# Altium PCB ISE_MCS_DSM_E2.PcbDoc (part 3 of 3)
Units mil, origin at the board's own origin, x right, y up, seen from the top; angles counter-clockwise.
Board outline 7874.02 x 2559.06 mil, 4 copper layers (Top Layer, MidLayer1, MidLayer2, Bottom Layer), stack 61.2 mil thick; 400 components, 190 nets, 1028 pads, 191 vias.
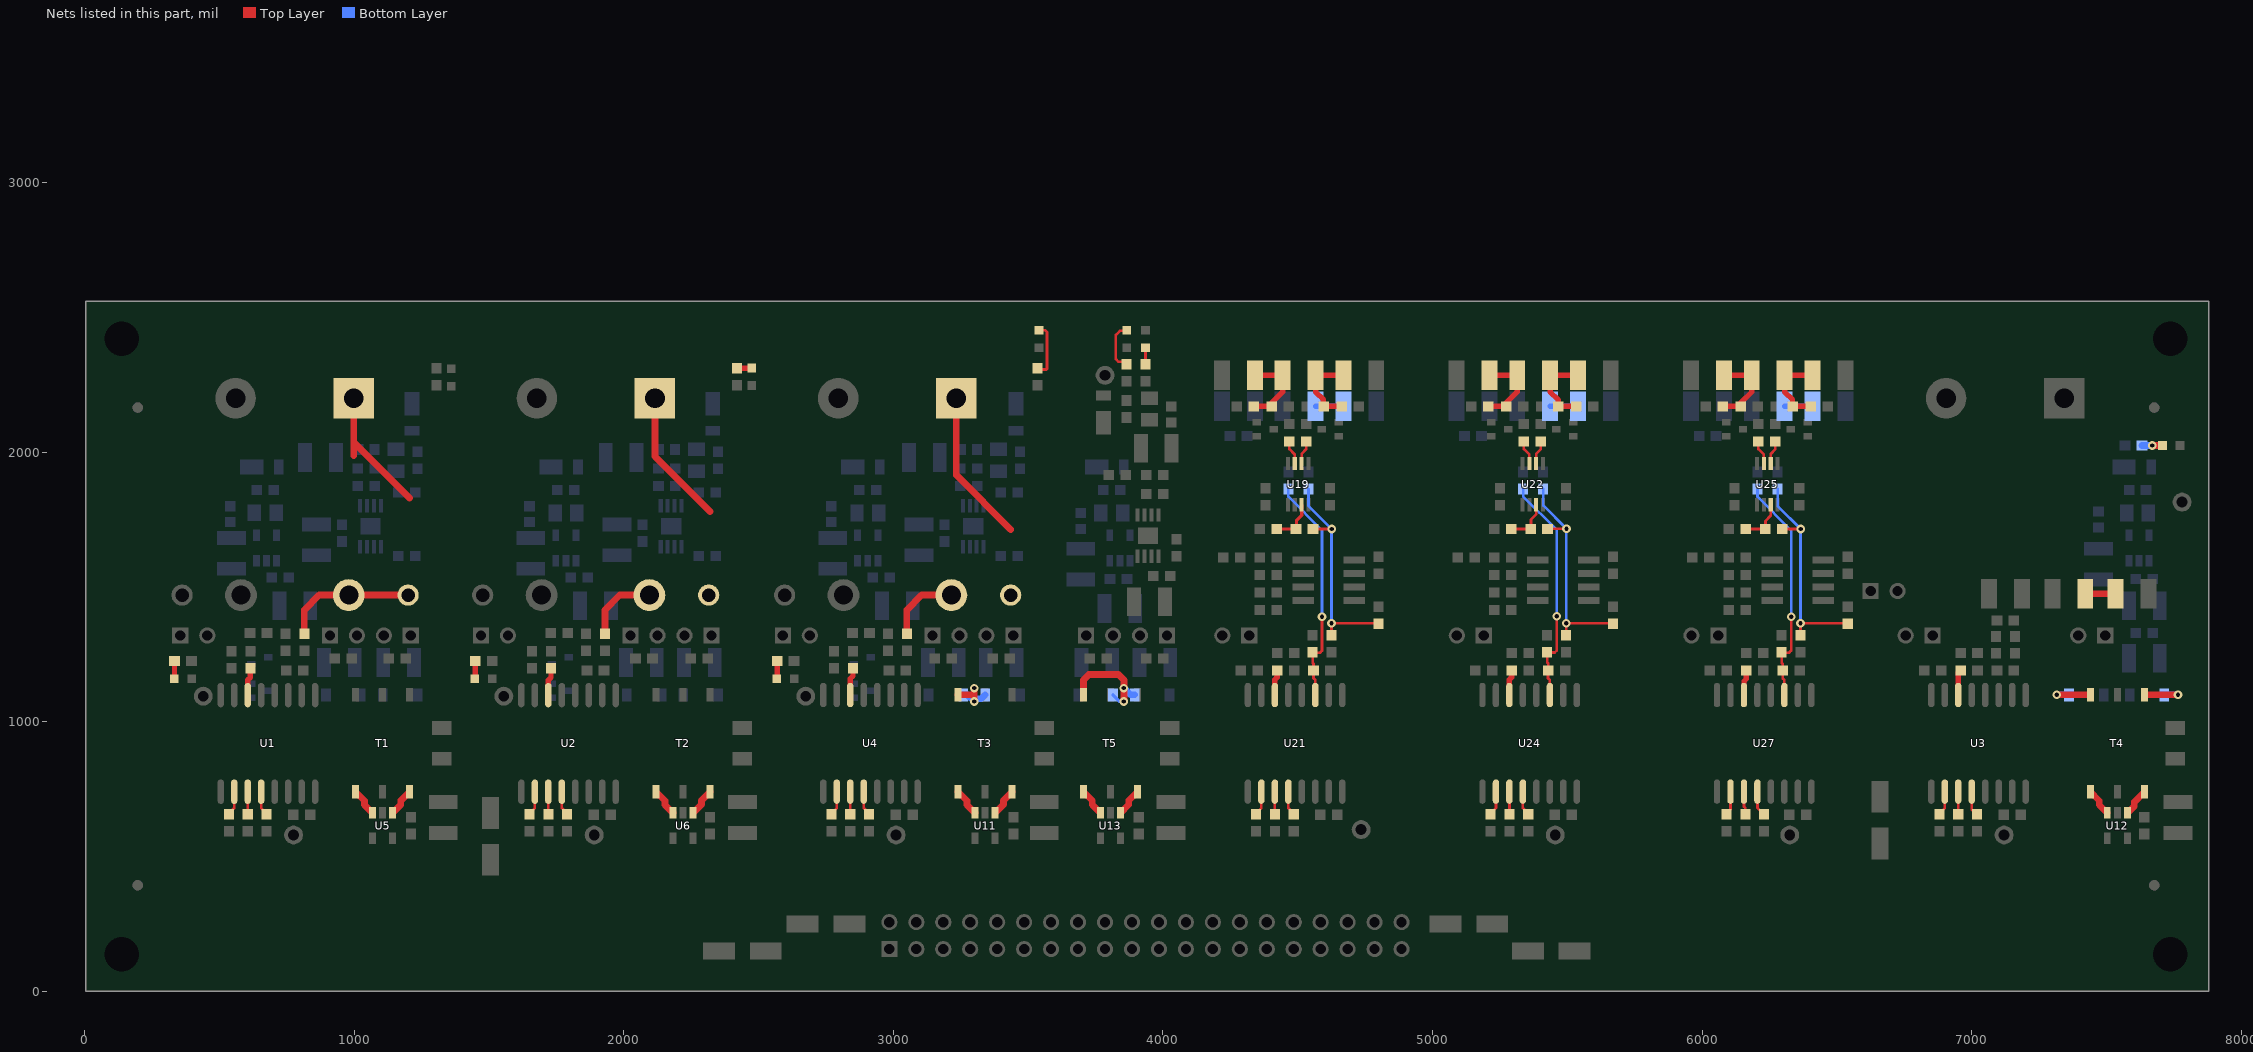
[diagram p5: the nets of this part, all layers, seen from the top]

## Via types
v1: diameter 32, hole 16, Top Layer to Bottom Layer, tented both sides, 191 vias

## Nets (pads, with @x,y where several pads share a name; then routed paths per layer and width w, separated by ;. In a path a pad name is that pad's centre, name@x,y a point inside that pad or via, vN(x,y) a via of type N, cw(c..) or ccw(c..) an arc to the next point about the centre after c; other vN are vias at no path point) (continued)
NetD14_1: D14.1 R35.1 | length 55.8
  Top Layer w20: R35.1@2420,2311.5 2472.98,2311.5 D14.1@2475,2309.48
NetD17_2: D17.2 R40.1 | length 65.4
  Top Layer w20: D17.2@332.52,1160 333.5,1160.98 R40.1@333.5,1225
NetD18_2: D18.2 R41.1 | length 65.4
  Top Layer w20: D18.2@1447.52,1160 1448.5,1160.98 R41.1@1448.5,1225
NetD19_2: D19.2 D23.1 T3.6 | length 212.7
  Top Layer w25: T3.6@3240,1099.84 3294.84,1099.84 3295,1100 ; v1(3300,1075) v1(3300,1125)
  Bottom Layer w25: D19.2@3259.47,1100 3275,1100 v1(3300,1075) 3300,1085 3325.53,1085 D23.1@3340.53,1100
NetD20_2: D20.2 T4.6 | length 170.6
  Top Layer w25: v1(7315.16,1099.84) T4.6@7440,1099.84
  Bottom Layer w25: v1(7315.16,1099.84) 7315,1100 D20.2@7360.53,1100
NetD21_2: D21.2 D24.1 T5.6 | length 403.5
  Top Layer w25: T5.6@3705,1099.84 3705,1155 3725,1175 3835,1175 3855,1155 v1(3855,1125) v1(3855,1075)
  Bottom Layer w12: D21.2@3814.47,1100 3839.47,1075 v1(3855,1075)
  Bottom Layer w25: v1(3855,1125) 3880,1100 D24.1@3895.53,1100
NetD22_2: D22.2 T4.4 | length 175.3
  Top Layer w25: T4.4@7640,1099.84 v1(7764.84,1099.84)
  Bottom Layer w25: D22.2@7714.47,1100 7764.68,1100 v1(7764.84,1099.84)
NetD27_1: D27.1 R42.1 | length 204.5
  Top Layer w10: R42.1@3535,2306.5 3566.5,2306.5 3570,2310 3570,2445 3562.52,2452.48 D27.1@3540,2452.48
NetD28_1: D28.1 R43.1 | length 180.4
  Top Layer w10: R43.1@3865,2335 3835,2335 3825,2345 3825,2435 3840,2450 D28.1@3865,2450
NetD32_2: D32.2 R48.1 | length 65.4
  Top Layer w20: D32.2@2567.52,1160.31 2568.5,1161.3 R48.1@2568.5,1225.31
NetD33_2: D33.2 R49.1 | length 76
  Top Layer w25: v1(7670,2025) D33.2@7707.52,2025
  Bottom Layer w25: R49.1@7631.5,2025 v1(7670,2025)
NetD34_2: D34.2 R50.1 | length 68.5
  Top Layer w10: R50.1@3935,2326.5 D34.2@3935,2387.52 D34.2@3935,2395
NetR5_1: R5.1 U1.12 | length 88.8
  Top Layer w10: U1.12@655,740.55 655,680 R5.1@675,660
NetR6_2: R6.2 U1.6 | length 103.8
  Top Layer w20: U1.6@605,1098.82 605,1155 615,1165 R6.2@615,1198.5
NetR7_1: R7.1 U1.11 | length 87.6
  Top Layer w10: U1.11@605,740.55 605,660 R7.1@610,655
NetR8_1: R8.1 U1.10 | length 95.9
  Top Layer w10: R8.1@530,655 555,680 U1.10@555,740.55
NetR13_1: R13.1 U2.12 | length 93.8
  Top Layer w10: U2.12@1770,740.55 1770,680 1790,660 R13.1@1790,656.5 R13.1@1790,655
NetR14_2: R14.2 U2.6 | length 103.8
  Top Layer w20: U2.6@1720,1098.82 1720,1155 1730,1165 R14.2@1730,1198.5
NetR15_1: R15.1 U2.11 | length 95.6
  Top Layer w10: R15.1@1720,645 U2.11@1720,740.55
NetR16_1: R16.1 U2.10 | length 98.8
  Top Layer w10: R16.1@1650,650 1650,660 1670,680 U2.10@1670,740.55
NetR17_2: R17.2 R18.1 | length 113
  Top Layer w25: R18.1@7421.02,1475 R17.2@7533.98,1475
NetR25_1: R25.1 U3.12 | length 94.2
  Top Layer w10: U3.12@7000,740.87 7000,675 R25.1@7020,655
NetR26_2: R26.2 U3.6 | length 94.4
  Top Layer w20: U3.6@6950,1099.13 6950,1181.5 R26.2@6958.5,1190
NetR27_1: R27.1 U3.11 | length 85.9
  Top Layer w10: R27.1@6950,655 R27.1@6950,656.5 U3.11@6950,740.87
NetR28_1: R28.1 U3.10 | length 94.2
  Top Layer w10: R28.1@6880,655 R28.1@6880,656.5 6880,660 6900,680 U3.10@6900,740.87
NetR30_1: R30.1 U4.12 | length 94.2
  Top Layer w10: U4.12@2890,740.87 2890,680 2910,660 R30.1@2910,656.5 R30.1@2910,655
NetR31_2: R31.2 U4.6 | length 103.5
  Top Layer w20: U4.6@2840,1099.13 2840,1160 2850,1170 R31.2@2850,1198.5
NetR32_1: R32.1 U4.11 | length 85.9
  Top Layer w10: R32.1@2840,655 R32.1@2840,656.5 U4.11@2840,740.87
NetR33_1: R33.1 U4.10 | length 89.2
  Top Layer w10: R33.1@2770,660 2790,680 U4.10@2790,740.87
NetR51_2: R51.2 R55.1 | length 103
  Bottom Layer w20: R55.1@4566.02,2170 R51.2@4668.98,2170
NetR52_2: R52.2 R53.1 R56.1 R61.1 | length 298.5
  Top Layer w20: R53.1@4663.5,2170 R56.1@4596.5,2170 4595,2170 4595,2195 4566.02,2223.98 R61.1@4566.02,2285 R52.2@4668.98,2285
NetR54_1: R54.1 R63.1 U19.7 | length 172.4
  Top Layer w12: R63.1@4420,1715 R63.1@4421.5,1715 R54.1@4493.5,1715 4495,1715 4495,1746.2 4514.4,1765.6 U19.7@4514.4,1804.4
NetR58_1: R58.1 U19.3 | length 90.6
  Top Layer w10: R58.1@4468.5,2040 4468.5,2011 4468.8,2011 4488.8,1991 U19.3@4488.8,1958
NetR58_2: R58.2 U19.2 | length 89.1
  Top Layer w10: U19.2@4514.4,1958 4514.4,1993.9 4531.5,2011 R58.2@4531.5,2040
NetR61_2: R61.2 R66.1 R70.1 R71.2 | length 307.3
  Top Layer w20: R71.2@4336.5,2170 R66.1@4390,2170 ; R70.1@4341.02,2285 R61.2@4443.98,2285 4443.98,2223.98 R66.1@4390,2170 ; R66.1@4403.5,2170 R66.1@4390,2170
NetR69_1: R69.1 U21.12 | length 94.2
  Top Layer w10: U21.12@4465,740.87 4465,680 4485,660 R69.1@4485,656.5 R69.1@4485,655
NetR72_2: R72.2 U21.6 | length 94.4
  Top Layer w20: U21.6@4415,1099.13 4415,1156.73 4423.5,1165.24 R72.2@4423.5,1190
NetR73_1: R73.1 U21.11 | length 85.9
  Top Layer w10: R73.1@4415,655 R73.1@4415,656.5 U21.11@4415,740.87
NetR74_1: R74.1 U21.10 | length 94.2
  Top Layer w10: R74.1@4345,655 R74.1@4345,656.5 4345,660 4365,680 U21.10@4365,740.87
NetR75_2: R75.2 R79.1 | length 103
  Bottom Layer w20: R79.1@5436.02,2170 R75.2@5538.98,2170
NetR76_2: R76.2 R77.1 R80.1 R87.1 | length 297.6
  Top Layer w20: R77.1@5533.5,2170 R80.1@5466.5,2170 5466.5,2193.5 5436.02,2223.98 R87.1@5436.02,2285 R76.2@5538.98,2285
NetR78_1: R78.1 R85.1 U22.7 | length 173
  Top Layer w10: R85.1@5290,1715 R85.1@5291.5,1715 R78.1@5363.5,1715 5365,1715 5365,1750 5384.4,1769.4 U22.7@5384.4,1804.4 ; U22.7@5385,1804.4 U22.7@5385,1805
NetR82_1: R82.1 U22.3 | length 90.6
  Top Layer w10: R82.1@5338.5,2040 5338.5,2011 5338.8,2011 5358.8,1991 U22.3@5358.8,1958
NetR82_2: R82.2 U22.2 | length 89.1
  Top Layer w10: U22.2@5384.4,1958 5384.4,1993.9 5401.5,2011 R82.2@5401.5,2040
NetR87_2: R87.2 R90.1 R94.1 R95.2 | length 303.2
  Top Layer w20: R95.2@5205,2170 R95.2@5206.5,2170 R90.1@5273.5,2170 5273.5,2183.5 5313.98,2223.98 R87.2@5313.98,2285 R94.1@5211.02,2285
NetR93_1: R93.1 U24.12 | length 94.2
  Top Layer w10: U24.12@5335,740.87 5335,680 5355,660 R93.1@5355,656.5 R93.1@5355,655
NetR96_2: R96.2 U24.6 | length 94.4
  Top Layer w20: U24.6@5285,1099.13 5285,1156.73 5293.5,1165.24 R96.2@5293.5,1190
NetR97_1: R97.1 U24.11 | length 85.9
  Top Layer w10: R97.1@5285,655 R97.1@5285,656.5 U24.11@5285,740.87
NetR98_1: R98.1 U24.10 | length 94.2
  Top Layer w10: R98.1@5215,655 R98.1@5215,656.5 5215,660 5235,680 U24.10@5235,740.87
NetR99_2: R99.2 R103.1 | length 103
  Bottom Layer w20: R103.1@6306.02,2170 R99.2@6408.98,2170
NetR100_2: R100.2 R101.1 R104.1 R111.1 | length 297
  Top Layer w20: R104.1@6335,2170 6335,2195 6306.02,2223.98 R111.1@6306.02,2285 R100.2@6408.98,2285 ; R104.1@6336.5,2170 R101.1@6403.5,2170
NetR102_1: R102.1 R109.1 U25.7 | length 170.9
  Top Layer w10: R109.1@6161.5,1715 R102.1@6233.5,1715 6235,1715 6235,1745 6254.4,1764.4 U25.7@6254.4,1804.4
NetR106_1: R106.1 U25.3 | length 90.6
  Top Layer w10: R106.1@6208.5,2040 6208.5,2011 6208.8,2011 6228.8,1991 U25.3@6228.8,1958
NetR106_2: R106.2 U25.2 | length 89.1
  Top Layer w10: U25.2@6254.4,1958 6254.4,1993.9 6271.5,2011 R106.2@6271.5,2040
NetR111_2: R111.2 R114.1 R118.1 R119.2 | length 301.7
  Top Layer w20: R119.2@6076.5,2170 R114.1@6143.5,2170 6143.5,2183.5 6183.98,2223.98 R111.2@6183.98,2285 R118.1@6081.02,2285
NetR117_1: R117.1 U27.12 | length 96.2
  Top Layer w10: U27.12@6205,740.87 6205,680 R117.1@6230,655
NetR120_2: R120.2 U27.6 | length 94.4
  Top Layer w20: U27.6@6155,1099.13 6155,1150 6163.5,1158.5 R120.2@6163.5,1190
NetR121_1: R121.1 U27.11 | length 82.9
  Top Layer w10: U27.11@6155,740.87 6155,685 6160,680 R121.1@6160,660
NetR122_1: R122.1 U27.10 | length 92.1
  Top Layer w10: R122.1@6090,655 R122.1@6090,656.5 6090,660 6105,675 U27.10@6105,740.87
NetT1_1: T1.1 U5.3 | length 103.7
  Top Layer w25: T1.1@1005,740 1038,707 1038,691.84 U5.3@1067.6,662.24
NetT1_3: T1.3 U5.1 | length 103.7
  Top Layer w25: U5.1@1142.4,662.24 1173,692.84 1173,708 T1.3@1205,740
NetT2_1: T2.1 U6.3 | length 103.7
  Top Layer w25: T2.1@2120,740 2153,707 2153,691.84 U6.3@2182.6,662.24
NetT2_3: T2.3 U6.1 | length 103.7
  Top Layer w25: U6.1@2257.4,662.24 2288,692.84 2288,708 T2.3@2320,740
NetT3_1: T3.1 U11.3 | length 103.7
  Top Layer w25: T3.1@3240,740 3273,707 3273,691.84 U11.3@3302.6,662.24
NetT3_3: T3.3 U11.1 | length 103.7
  Top Layer w25: U11.1@3377.4,662.24 3408,692.84 3408,708 T3.3@3440,740
NetT4_1: T4.1 U12.3 | length 103.7
  Top Layer w25: T4.1@7440,740 7473,707 7473,691.84 U12.3@7502.6,662.24
NetT4_3: T4.3 U12.1 | length 103.7
  Top Layer w25: U12.1@7577.4,662.24 7603,687.84 7603,703 T4.3@7640,740
NetT5_1: T5.1 U13.3 | length 103.7
  Top Layer w25: T5.1@3705,740 3738,707 3738,691.84 U13.3@3767.6,662.24
NetT5_3: T5.3 U13.1 | length 103.7
  Top Layer w25: U13.1@3842.4,662.24 3873,692.84 3873,708 T5.3@3905,740
U_OUT: J2.1 R1.1 R2.1 R3.1 | length 967
  Top Layer w25: R1.1@815,1326.5 815,1415 870,1470 R2.1@980,1470 R3.1@1200,1470 R3.1@1205,1470 ; 998,1987 J2.1@998,2160 ; 998,2037 1205,1830
V_OUT: J4.1 R9.1 R10.1 R11.1 | length 741
  Top Layer w25: R9.1@1930,1326.5 1930,1415 1985,1470 R10.1@2095,1470 ; J4.1@2115.4,2160 2115.4,1984.6 2320,1780
VOLT_U_PH: R54.2 R57.2 R59.2 R60.1 | length 823.6
  Top Layer w10: R54.2@4556.5,1715 v1(4625.75,1715) ; R60.1@4625,1321.5 v1(4625,1365) 4800,1365 R59.2@4800,1363.5
  Bottom Layer w10: R57.2@4540,1863.5 4540,1800.75 v1(4625.75,1715) 4625,1714.25 v1(4625,1365)
VOLT_U_PH_N: C115.2 R65.2 R67.1 U21.3 | length 848.4
  Top Layer w10: U21.3@4565,1105 4565,1155 4558.5,1161.5 C115.2@4558.5,1190 4558.5,1214.7 4555,1218.2 R67.1@4555,1258.5 4557.5,1256 4582.2,1256 4590,1263.8 v1(4590,1390)
  Bottom Layer w10: R65.2@4465,1863.5 4465,1835 4590,1710 v1(4590,1390)
VOLT_V_PH: R78.2 R81.2 R83.2 R84.1 | length 823.6
  Top Layer w10: R78.2@5427.39,1715.9 v1(5496.64,1715.9) ; R84.1@5495.9,1322.39 v1(5495.9,1365.9) 5670.9,1365.9 R83.2@5670.9,1364.4
  Bottom Layer w10: R81.2@5410.9,1864.4 5410.9,1801.64 v1(5496.64,1715.9) 5495.9,1715.15 v1(5495.9,1365.9)
VOLT_V_PH_N: C127.2 R89.2 R91.1 U24.3 | length 848.4
  Top Layer w10: C127.2@5428.5,1190 5428.5,1161.5 5435,1155 U24.3@5435,1105 ; C127.2@5429.4,1190.9 5429.4,1215.59 5425.9,1219.1 5425.9,1259.4 5428.4,1256.9 5453.1,1256.9 5460.9,1264.7 v1(5460.9,1390.9)
  Bottom Layer w10: R89.2@5335.9,1864.4 5335.9,1835.9 5460.9,1710.9 v1(5460.9,1390.9)
VOLT_W_PH: R102.2 R105.2 R107.2 R108.1 | length 823.6
  Top Layer w10: R102.2@6296.5,1715 v1(6365.75,1715) ; R108.1@6365,1321.5 v1(6365,1365) 6540,1365 R107.2@6540,1363.5
  Bottom Layer w10: R105.2@6280,1863.5 6280,1800.75 v1(6365.75,1715) 6365,1714.25 v1(6365,1365)
VOLT_W_PH_N: C139.2 R113.2 R115.1 U27.3 | length 843.4
  Top Layer w10: U27.3@6305,1110 6305,1155 6298.5,1161.5 C139.2@6298.5,1190 6298.5,1214.7 6295,1218.2 R115.1@6295,1258.5 6297.5,1256 6322.2,1256 6330,1263.8 v1(6330,1390)
  Bottom Layer w10: R113.2@6205,1863.5 6205,1835 6330,1710 v1(6330,1390)
W_OUT: J8.1 R20.1 R23.1 R24.1 | length 806.2
  Top Layer w25: R20.1@3050,1326.5 3050,1415 3105,1470 R23.1@3215,1470 ; J8.1@3233.51,2160 3233.51,1915 3435,1713.51
pads on no net: FID1.1 FID2.1 FID3.1 FID4.1 FID5.1 FID6.1 FID7.1 FID8.1 LBL1.0 Logo1.0 MH1.1 MH2.1 MH3.1 MH4.1 T1.5 T2.5 T3.5 T5.5 U1.1 U1.4 U1.5 U1.15 U2.1 U2.4 U2.5 U2.15 U3.1 U3.4 U3.5 U3.15 U4.1 U4.4 U4.5 U4.15 U7.7 U8.7 U9.4 U9.5 U10.4 U10.5 U14.7 U15.7 U16.4 U16.5 U17.4 U17.5 U18.4 U18.5 U20.1 U20.5 U20.8 U21.1 U21.4 U21.5 U21.15 U23.1 U23.5 U23.8 U24.1 U24.4 U24.5 U24.15 U26.1 U26.5 U26.8 U27.1 U27.4 U27.5 U27.15

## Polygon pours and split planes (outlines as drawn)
+5.0V_VDC on MidLayer1 "MidLayer1-No Net 8" (solid, remove dead copper, pour order 73): 6695,2075 7835,2075 7835,1055 6695,1055
-5.0V_PH on MidLayer1 "MidLayer1-No Net 1" (solid, remove dead copper, pour order 52): 3750,2335 4010,2335 4010,2169.97 4075,2104.97 4075.03,2105 6580,2105 6580,1055 4175,1055 4155,1075 4155,1630 4025,1760 3750,1760
+3.3V_DVDD on MidLayer1 "MidLayer1-No Net" (solid, remove dead copper, pour order 45): 45,785 7830,785 7830,45 45,45
U_OUT on MidLayer1 "MidLayer1-No Net 2" (solid, remove dead copper, pour order 56): 860,2275 785,2200 785,1470 850,1405 1195,1405 1260,1470 1259.06,2090.94 1075,2275
GND_USH on MidLayer1 "MidLayer1-No Net 5" (solid, remove dead copper, pour order 65): 615,1405 680,1470 680,2205 610,2275 515,2275 305,2065 305,1470 370,1405
GND_VSH on MidLayer1 "MidLayer1-No Net 6" (solid, remove dead copper, pour order 66): 1735,1405 1800,1470 1800,2200 1725,2275 1640,2275 1420,2055 1420,1470 1485,1405
V_OUT on MidLayer1 "MidLayer1-No Net 3" (solid, remove dead copper, pour order 57): 1965,1405 1900,1470 1900,2200 1975,2275 2190.04,2275 2375.04,2090 2375,2089.96 2375,1470 2310,1405
GND_WSH on MidLayer1 "MidLayer1-No Net 7" (solid, remove dead copper, pour order 67): 2855,1405 2920,1470 2920,2198.11 2843.11,2275 2758.11,2275 2535,2051.89 2535,1470 2600,1405
W_OUT on MidLayer1 "MidLayer1-No Net 4" (solid, remove dead copper, pour order 58): 3100,2275 3025,2200 3025,1470 3090,1405 3430,1405 3495,1470 3495,2090 3310,2275
DCLINK_N on MidLayer2 "Bottom Layer-No Net 4" (solid, remove dead copper, pour order 44): 6695,1055 6695,2300 6755,2360 7595,2360 7835,2120 7835,1055
DGND on MidLayer2 "Bottom Layer-No Net" (solid, remove dead copper, pour order 46): 45,785 7830,785 7830,45 45,45
GND_USH on MidLayer2 "MidLayer2-No Net 2" (solid, remove dead copper, pour order 68): 305,1045 1250,1045 1250,2075 305,2075
GND_VSH on MidLayer2 "MidLayer2-No Net 2" (solid, remove dead copper, pour order 69): 1420,1045 2365,1045 2365,2075 1420,2075
GND_WSH on MidLayer2 "MidLayer2-No Net 2" (solid, remove dead copper, pour order 70): 2540,1045 3485,1045 3485,2075 2540,2075
GND_PH on MidLayer2 "MidLayer2-No Net" (solid, remove dead copper, pour order 50): 3650,1055 3650,2075 6580,2075 6580,1055
+5.0V_PH on Bottom Layer "MidLayer2-No Net 1" (solid, remove dead copper, pour order 51): 3780,2060 3800,2080 3860,2080 4135,1805 4135,1675 4155,1655 4155,1075 4175,1055 6580,1055 6580,2000 6455,2000 6455,2105 5895,2105 5895,2000 5585,2000 5585,2105 5030,2104.74 5030,1995 4715,1995 4715,2105 4075,2104.97 4010,2170.64 4010,2335 3750,2335 3750,2200 3690,2140 3690,1975 3780,1975
DCLINK_N on Bottom Layer "Bottom Layer-No Net 4" (solid, remove dead copper, pour order 42): 7375,1555 7525,1555 7540,1540 7540,1455 7430,1345 7430,1295 7415,1280 7375,1280 7360,1295 7360,1540
+5V_CNTL on Bottom Layer "Bottom Layer-No Net 1" (solid, remove dead copper, pour order 47): 45,785 7830,785 7830,45 45,45
GND_PH on Bottom Layer "Bottom Layer-No Net 2" (solid, remove dead copper, pour order 49): 3905,1670 3920,1655 4075,1655 4095,1675 4095,1820 3850,2065 3810,2065 3795,2050 3795,2005 3815,1985 3815,1740 3885,1740 3905,1720
DCLINK_N on Bottom Layer "Bottom Layer-No Net 4" (solid, remove dead copper, pour order 36): 7640,1180 7660,1160 7815,1160 7835,1180 7835,1954.65 7815,1974.65 7815,1975 7645,1975 7625,1955 7625,1690 7650,1660 7650,1495 7640,1485
+5.0V_VDC on Bottom Layer "Bottom Layer-No Net 4" (solid, remove dead copper, pour order 37): 7590,2045 7590,1995 7610,1975 7610,1755 7595,1740 7530,1740 7510,1760 7450,1760 7450,1985 7465,2000 7505,2000 7550,2045
+6V_VDC on Bottom Layer "Bottom Layer-No Net 4" (solid, remove dead copper, pour order 38): 7615,1575 7555,1515 7555,1445 7465,1355 7465,1080 7470,1075 7605,1075 7615,1085 7615,1090 7630,1105 7630,1190 7630,1495 7630,1575
NetC102_2 on Bottom Layer "Bottom Layer-No Net 4" (solid, remove dead copper, pour order 43): 7595,1620 7595,1575 7560,1575 7520,1615 7415,1615 7415,1720 7435,1740 7500,1740 7510,1730 7525,1715 7525,1690
GND_USH on Bottom Layer "Bottom Layer-No Net 3" (solid, remove dead copper, pour order 61): 1140,1160 975,1160 975,1376.23 675,1376.23 675,1401.37 485,1401.37 485,2040 1185,2040 1255,1969.6 1255,1667.89 1230,1642.74 1010,1642.74 1010,1491.89 1060,1441.6 1060,1371.2 1080,1351.09 1125,1351.09 1140,1336
-6V_USH on Bottom Layer "Top Layer-No Net 7" (solid, remove dead copper, pour order 41): 1200,1390 1160,1390 1120,1430 1120,1590 1105,1605 960,1605 960,1620 1030,1620 1030,1675 990,1675 975,1690 805,1690 805,1585 820,1570 1025,1570 1080,1515 1080,1390 1180,1290 1180,1060 1260,1060 1260,1330
-6V_VSH on Bottom Layer "Top Layer-No Net 7" (solid, remove dead copper, pour order 40): 2315,1390 2275,1390 2235,1430 2235,1590 2220,1605 2075,1605 2075,1620 2145,1620 2145,1675 2105,1675 2090,1690 1920,1690 1920,1585 1935,1570 2140,1570 2195,1515 2195,1390 2295,1290 2295,1060 2375,1060 2375,1330
-6V_WSH on Bottom Layer "Top Layer-No Net 7" (solid, remove dead copper, pour order 39): 3435,1390 3395,1390 3355,1430 3355,1590 3340,1605 3195,1605 3195,1620 3265,1620 3265,1675 3225,1675 3210,1690 3040,1690 3040,1585 3055,1570 3260,1570 3315,1515 3315,1390 3415,1290 3415,1060 3495,1060 3495,1330
GND_VSH on Bottom Layer "Bottom Layer-No Net 3" (solid, remove dead copper, pour order 60): 2255,1160 2090,1160 2090,1376.23 1790,1376.23 1790,1401.37 1600,1401.37 1600,2040 2300,2040 2370,1969.6 2370,1667.89 2345,1642.74 2125,1642.74 2125,1491.89 2175,1441.6 2175,1371.2 2195,1351.09 2240,1351.09 2255,1336
GND_WSH on Bottom Layer "Bottom Layer-No Net 3" (solid, remove dead copper, pour order 59): 3375,1160 3210,1160 3210,1376.23 2910,1376.23 2910,1401.37 2720,1401.37 2720,2040 3420,2040 3490,1969.6 3490,1667.89 3465,1642.74 3245,1642.74 3245,1491.89 3295,1441.6 3295,1371.2 3315,1351.09 3360,1351.09 3375,1336
GND_PH on Top Layer "Top Layer-No Net" (solid, remove dead copper, pour order 48): 3985,2145 3975,2155 3750,2155 3750,1990 3750,1395 3770,1375 3770,1215 3960,1215 3960,1475 3930,1505 3900,1505 3885,1520 3885,1640 4115,1640 4115,1715 4100,1730 3965,1730 3965,2065 3965,2066 3985,2086
GND_USH on Top Layer "Top Layer-No Net 4" (solid, remove dead copper, pour order 62): 560,1410 680,1530 680,2195 600,2275 522.6,2275 305,2058 305,1465 360,1410
U_OUT on Top Layer "Top Layer-No Net 1" (solid, remove dead copper, pour order 53): 1225,1410 995,1410 905,1500 820,1500 785,1535 785,2200 860,2275 1075,2275 1260,2090 1259.06,2089.06 1259.06,1514.06 1260,1445
GND_VSH on Top Layer "Top Layer-No Net 5" (solid, remove dead copper, pour order 63): 1680,1410 1800,1530 1800,2200 1725,2275 1640,2275 1420,2055 1420,1505 1419.33,1455 1465,1410
V_OUT on Top Layer "Top Layer-No Net 2" (solid, remove dead copper, pour order 54): 1975,2275 1900,2200 1900,1535 1935,1500 2020,1500 2110,1410 2335,1410 2374.06,1450 2375,2090 2190,2275
GND_WSH on Top Layer "Top Layer-No Net 6" (solid, remove dead copper, pour order 64): 2843.11,2275 2920,2198.11 2920,1530 2800,1410 2580,1410 2539.33,1450 2537.44,2054.33 2758.11,2275
W_OUT on Top Layer "Top Layer-No Net 3" (solid, remove dead copper, pour order 55): 3310,2275 3100,2275 3025,2200 3025,1530 3055,1500 3140,1500 3230,1410 3445,1410 3495,1460 3495,2090

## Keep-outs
Keep-Out Layer:
  circle w78.74: c7736.22,137.8 r118.11
  circle w78.74: c137.8,137.8 r118.11
  lines w10: -5,0 -5,3450 ; 0,-5 4950,-5
  text ".Layer_Name" at 577,-858.49 h60

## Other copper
Top Layer:
  region net -6V_PH: 3980,1500 3980,1215 3990,1205 4035,1205 4050,1220 4050,1491.2 4041.2,1500
  region net NetD21_2: 3835,1070 3850,1055 3860,1055 3875,1070 3875,1180 3855,1200 3685,1200 3670,1185 3670,1075 3690,1055 3720,1055 3740,1075 3740,1125 3750,1135 3825,1135 3835,1125
  region net NetC89_2: 3975,1740 3975,2060 4000,2085 4000,2120 4010,2130 4050,2130 4060,2120 4060,1755 4045,1740
  region net -5.0V_PH: 4010,2150 4050,2150 4060,2160 4060,2180 4010,2230 3910,2230 3900,2240 3900,2275 3890,2285 3845,2285 3805,2325 3765,2325 3750,2310 3750,2190 3770,2170 3990,2170
  region net NetD7_2: 1080,1070 1070,1060 995,1060 985,1070 985,1130 995,1140 1070,1140 1080,1130
  region net NetD8_2: 2195,1070 2185,1060 2110,1060 2100,1070 2100,1130 2110,1140 2185,1140 2195,1130
  region net NetD19_2: 3315,1070 3305,1060 3230,1060 3220,1070 3220,1130 3230,1140 3305,1140 3315,1130
  region net GND_USH: 970,1350 985,1365 1135,1365 1150,1350 1150,1215 1220,1145 1220,1070 1210,1060 1170,1060 1160,1070 1160,1115 1095,1180 985,1180 970,1195
  region net GND_VSH: 2085,1355 2100,1370 2250,1370 2265,1355 2265,1220 2335,1150 2335,1075 2325,1065 2285,1065 2275,1075 2275,1120 2210,1185 2100,1185 2085,1200
  region net GND_WSH: 3205,1355 3220,1370 3370,1370 3385,1355 3385,1220 3455,1150 3455,1075 3445,1065 3405,1065 3395,1075 3395,1120 3330,1185 3220,1185 3205,1200
  text ".Layer_Name" at 577,-858.49 h60
MidLayer1:
  text ".Layer_Name" at 577,-858.49 h60
MidLayer2:
  text ".Layer_Name" at 577,-858.49 h60
Bottom Layer:
  region net +5.0V_PH: 3670,1755 3730,1755 3745,1740 3800,1740 3800,1975 3780,1995 3690,1995 3660,1965 3660,1765
  region net -6V_PH: 3980,1090 3995,1075 4045,1075 4065,1095 4065,1345 4050,1360 3995,1360 3980,1345
  region net +6V_PH: 3665,1075 3685,1055 3725,1055 3745,1075 3745,1335 3775,1365 3815,1365 3835,1385 3835,1555 3832.8,1557.2 3782.2,1557.2 3760,1535 3760,1481.72 3663.8,1385.52 3663.8,1158.28
  region net NetC108_2: 3670,1735 3640,1705 3640,1600 3665,1575 3815,1575 3815,1620 3715,1720 3715,1735
  region net GND_PH: 3750,1565 3750,1490 3715,1455 3650,1455 3640,1465 3640,1555 3650,1565
  region net GND_PH: 3785,1350 3770,1335 3770,1180 3785,1165 3940,1165 3955,1180 3955,1445 3885,1515 3850,1515 3845,1510 3845,1365 3830,1350
  region net +5.0V_USH: 485,1795 500,1780 560,1780 600,1740 665,1740 665,1975 505,1975 485,1955
  region net -5.0V_USH: 1055,1980 1257.64,1980 1257.64,2100 1140,2100 1140,2045 1130,2035 1055,2035
  region net NetC42_2: 1035,2035 1035,1855 1030,1850 1030,1777 1003,1777 990,1790 930,1790 905,1815 905,2035
  region net NetD7_2: 1125,1130 1125,1070 1115,1060 1015,1060 1005,1070 1005,1130 1015,1140 1115,1140
  region net NetD8_2: 2240,1130 2240,1070 2230,1060 2130,1060 2120,1070 2120,1130 2130,1140 2230,1140
  region net NetD19_2: 3360,1130 3360,1070 3350,1060 3250,1060 3240,1070 3240,1130 3250,1140 3350,1140
  region net NetD21_2: 3915,1130 3915,1070 3905,1060 3805,1060 3795,1070 3795,1130 3805,1140 3905,1140
  pour cut-out: 703.29,1620 703.29,1661.71 705,1710 685,1730 620,1730 620,1620
  pour cut-out: 1818.29,1620 1818.29,1661.71 1820,1710 1800,1730 1735,1730 1735,1620
  pour cut-out: 2937.49,1620 2937.49,1661.71 2939.2,1710 2919.2,1730 2854.2,1730 2854.2,1620
  pour cut-out: 865,1570 865,1350 1080,1350 1080,1515 1025,1570
  pour cut-out: 670,1375 895,1375 895,1350 670,1350
  region net NetC56_2: 560,1760 610,1710 610,1665 650,1625 650,1575 625,1575 625,1605 610,1620 495,1620 485,1630 485,1745 500,1760
  pour cut-out: 640,1560 640,1395 645,1395 645,1560
  region net +6V_USH: 662,1620 662,1528 680,1510 680,1295 700,1275 810,1275 840,1245 840,1070 850,1060 930,1060 940,1070 940,1350 765,1350 750,1365 750,1485 725,1485 715,1495 715,1555 700,1555 688,1567 688,1620
  region net +6V_VSH: 1772,1620 1772,1525 1795,1502 1795,1295 1815,1275 1925,1275 1955,1245 1955,1070 1965,1060 2045,1060 2055,1070 2055,1350 1880,1350 1865,1365 1865,1485 1840,1485 1830,1495 1830,1555 1815,1555 1798,1572 1798,1620
  pour cut-out: 1755,1560 1755,1395 1760,1395 1760,1560
  pour cut-out: 1785,1375 2010,1375 2010,1350 1785,1350
  pour cut-out: 1980,1570 1980,1350 2195,1350 2195,1515 2140,1570
  pour cut-out: 3100,1570 3100,1350 3315,1350 3315,1515 3260,1570
  pour cut-out: 2905,1375 3130,1375 3130,1350 2905,1350
  pour cut-out: 2875,1560 2875,1395 2880,1395 2880,1560
  region net +6V_WSH: 2892,1620 2892,1525 2915,1502 2915,1295 2935,1275 3045,1275 3075,1245 3075,1070 3085,1060 3165,1060 3175,1070 3175,1350 3000,1350 2985,1365 2985,1485 2960,1485 2950,1495 2950,1555 2935,1555 2918,1572 2918,1620
  region net NetC58_2: 1670,1759.5 1720,1709.5 1720,1664.5 1760,1624.5 1760,1574.5 1735,1574.5 1735,1604.5 1720,1619.5 1605,1619.5 1595,1629.5 1595,1744.5 1610,1759.5
  region net NetC100_2: 2790,1760 2840,1710 2840,1665 2880,1625 2880,1575 2855,1575 2855,1605 2840,1620 2725,1620 2715,1630 2715,1745 2730,1760
  region net +5.0V_VSH: 1595,1794.5 1610,1779.5 1670,1779.5 1710,1739.5 1775,1739.5 1775,1974.5 1615,1974.5 1595,1954.5
  region net +5.0V_WSH: 2715,1795 2730,1780 2790,1780 2830,1740 2895,1740 2895,1975 2735,1975 2715,1955
  region net NetC45_2: 2150,2035 2150,1855 2145,1850 2145,1777 2118,1777 2105,1790 2045,1790 2020,1815 2020,2035
  region net NetC86_2: 3270.8,2035 3270.8,1855 3265.8,1850 3265.8,1777 3238.8,1777 3225.8,1790 3165.8,1790 3140.8,1815 3140.8,2035
  region net -5.0V_VSH: 2170,1980 2372.64,1980 2372.64,2100 2255,2100 2255,2045 2245,2035 2170,2035
  region net -5.0V_WSH: 3290.8,1980 3493.44,1980 3493.44,2100 3375.8,2100 3375.8,2045 3365.8,2035 3290.8,2035
  text ".Layer_Name" at 577,-858.49 h60

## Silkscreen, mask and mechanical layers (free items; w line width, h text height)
Top Overlay:
  circle w10: c6628,1553 r1
  circle w10: c1014,2441 r22.2
  circle w10: c2127,2444 r22.2
  circle w10: c3247,2439 r22.2
  circle w10: c301,1367 r1
  circle w10: c874,1260 r1
  circle w10: c1259,1366 r1
  circle w10: c1416,1366 r1
  circle w10: c1981,1268 r1
  circle w10: c2377,1365 r1
  circle w10: c2534,1366 r1
  circle w10: c3108,1262 r1
  circle w10: c3493,1270 r1
  circle w10: c3667,1372 r1
  circle w10: c4070,1271 r1
  circle w10: c4394,1318 r1
  circle w10: c5257,1320 r1
  circle w10: c6128,1320 r1
  circle w10: c6910,1365 r1
  circle w10: c7557,1364 r1
  circle w10: c7329,2446 r22.2
  circle w6: c4562.93,1995 r7.07
  circle w6: c535,325 r33.54
  circle w6: c1650,305 r33.54
  circle w6: c2610,625 r33.54
  circle w6: c545,1330 r33.54
  circle w6: c1660,1330 r33.54
  circle w6: c2780,1335 r33.54
  circle w6: c1167,687 r1.53
  circle w6: c2285,686 r2.24
  circle w6: c3404,686 r2
  circle w6: c3869,685 r2
  circle w6: c7603,687.84 r2.24
  region: 7375,365 7375,265 7497.5,265 7497.5,365
  lines w6: 429,1176 429.5,1175.5 ; 446,1200 447,1201 ; 470,1175 472,1175 ; 500,1375 525,1375 855,1375 855,1165 845,1155 520,1155 505,1170 505,1285 ; 2566,98 2589,98 ; 2578,86 2578,109 ; 2660,1167 2660.1,1167.1 2681.79,1167.1 ; 2883,315 2907,315 ; 2894,306 2894,325 ; 3875.9,1610.9 3875.9,1766.5 ; 4010.9,1610.9 4010.9,1766.5 ; 4439.1,1805.3 4439.1,1960.9 ; 4520,1415 4710,1415 ; 4520,1630 4710,1630 ; 4574.1,1805.3 4574.1,1960.9 ; 4983,313 5009,313 ; 4994,331 4994,299 4995,298 ; 5280,92 5299,92 ; 5290,79 5290,103 ; 5309.1,1805.3 5309.1,1960.9 ; 5390,1415 5580,1415 ; 5390,1630 5580,1630 ; 5444.1,1805.3 5444.1,1960.9 ; 6178.2,1804.4 6178.2,1960 ; 6260,1415 6450,1415 ; 6260,1630 6450,1630 ; 6313.2,1804.4 6313.2,1960 ; 500,147.5 500,392.5 865,392.5 865,147.5 500,147.5 ; 1610,147.5 1610,392.5 1990,392.5 1990,147.5 1610,147.5 ; 1625,1165 1625,1355 1645,1375 1955,1375 1965,1365 1965,1155 1635,1155 1625,1165 ; 2502,375 2743,375 2743,670 2502,670 2502,375 ; 2740,1160 2740,1360 2760,1380 3070,1380 3095,1355 3095,1175 3074,1154 2746,1154 2740,1160
  lines w8: 429.5,1175.5 446,1175.5 ; 446,1200 446,1151 470,1175
  lines w10: 2920.01,97.19 4950.01,97.19 ; 2920.01,-2.81 4950.01,-2.81 4950.01,302.19 4947.81,300 3085,300 2922.2,300 2920.01,302.19 2920.01,-2.81
  text "/" at 1335,1470 h40
  text "/" at 2440,1470 h40
  text "/" at 165,1460 h40
  text "C" at 2770,1320 h35
  text "A" at 535,1315 h35
  text "B" at 1650,1315 h35
  text "C" at 2600,610 h35
  text "2" at 2970,320 h40
  text "40" at 4870,320 h40
  text "A" at 525,310 h35
  text "B" at 1640,290 h35
  text "ISE_MCS_DSM_E2" at 6520,280 h60
  text "TIDA-00171" at 6535,145 h60
  text "1" at 2880,75 h40
  text "39" at 4970,75 h40
  text ".Layer_Name" at 577,-858.49 h60
Bottom Overlay:
  region: 6543.75,215 6543.75,115 6666.25,115 6666.25,215
  lines w6: 990,1650 990,1805 ; 1060,2050 1100,2090 1100,2285 1100,2290 ; 1130,1650 1130,1805 ; 2105,1650 2105,1805 ; 2185,2060 2215,2090 2215,2285 2201,2299 ; 2245,1650 2245,1805 ; 3225,1650 3225,1805 ; 3311,2304 3325,2290 3325,2060 ; 3365,1650 3365,1805
  text "ISE_MCS_DSM_E2" at 7520,137 h60
  text ".Layer_Name" at 577,-858.49 h40
Top Paste:
  text ".Layer_Name" at 577,-858.49 h60
Bottom Paste:
  text ".Layer_Name" at 577,-858.49 h60
Top Solder:
  text ".Layer_Name" at 577,-858.49 h60
  text ".Layer_Name" at 577,-858.49 h60
Bottom Solder:
  text ".Layer_Name" at 577,-858.49 h60
Drill Guide:
  text ".Layer_Name" at 577,-858.49 h60
M1 Board Outline:
  lines w10: 0,0 0,2559.06 7874.02,2559.06 7874.02,0 0,0
  text ".Layer_Name" at 567,-861 h60
M2 Board Dimensions:
  rectangle: -0.5,-285.5 124.5,-160.5
  rectangle: 124.5,-410.5 499.5,-285.5
  lines w7: -0.5,-285.5 999.5,-285.5 ; 124.5,-410.5 124.5,-160.5 ; 249.5,-410.5 249.5,-160.5 ; 499.5,-410.5 499.5,-160.5 ; 749.5,-410.5 749.5,-160.5 ; -0.5,-410.5 999.5,-410.5 999.5,-160.5 -0.5,-160.5 -0.5,-410.5
  lines w10: -0.5,-475.5 -0.5,-455.5 ; 59.5,-485.5 -0.5,-465.5 ; 59.5,-445.5 -0.5,-465.5 ; 223.58,-465.5 -0.5,-465.5 ; 775.42,-465.5 999.5,-465.5 ; 939.5,-485.5 999.5,-465.5 ; 939.5,-445.5 999.5,-465.5 ; 999.5,-475.5 999.5,-455.5
  text "1000 (mil)" at 233.58,-501.49 h60
M3 3D STEP Top:
  text ".Layer_Name" at 577,-858.49 h60
M4 3D STEP Bottom:
  text ".Layer_Name" at 577,-858.49 h60
M5 Assembly Top:
  drawing of 175 lines, arcs and shapes, not listed
  text "J2" at 750,2445 h50
  text "J4" at 1867.4,2445 h50
  text "J8" at 2985.51,2445 h50
  text "J6" at 7081,2440 h50
  text "D28" at 3808,2425 h40 r90
  text "D34" at 4035,2425 h40 r90
  text "D27" at 3616,2404 h40 r90
  text "D13" at 1385.6,2141 h40 r90
  text "D14" at 2503,2141 h40 r90
  text "FB6" at 4048,2092 h36 r90
  text "D33" at 7720,1927 h50
  text "*" at 6592.97,1461 h40
  text "R11" at 1296,1446 h50
  text "R3" at 199,1443 h50
  text "R24" at 2398,1442 h50
  text "*" at 4321.97,1305 h40
  text "*" at 2552.97,1303 h40
  text "*" at 1440.97,1302 h40
  text "*" at 4018.97,1302 h40
  text "*" at 3678.97,1301 h40
  text "*" at 6059.97,1301 h40
  text "*" at 319.97,1300 h40
  text "*" at 883.97,1300 h40
  text "*" at 1214.97,1300 h40
  text "*" at 3110.97,1300 h40
  text "*" at 5200.97,1300 h40
  text "*" at 1990.97,1299 h40
  text "*" at 6851.97,1299 h40
  text "*" at 3453.97,1298 h40
  text "*" at 7496.97,1297 h40
  text "*" at 2328.97,1294 h40
  text "D17" at 212,1137 h40
  text "D17" at 2447,1137 h40
  text "D17" at 1338,1134 h40
  text "T4" at 7500,899 h50
  text "T1" at 1044,888 h50
  text "T2" at 2159,888 h50
  text "T3" at 3279,888 h50
  text "T5" at 3744,888 h50
  text "COMPONENTS MARKED 'DNP' SHOULD NOT BE POPULATED." at 1153.5,-318.5 h60
  text "ASSEMBLY VARIANT:" at 1153,-434 h60
  text ".VariantName" at 2189,-434 h60
  text "PCB VIEWED FROM TOP SIDE" at -228.5,-655.67 h60
  text "BOARD #:" at 2248,-655.67 h60
  text ".PRJ_Number" at 2793.5,-655.67 h60
  text "REV:" at 3638,-655.67 h60
  text "E2" at 3929.5,-655.67 h60
  text "SVN REV:" at 4476,-655.67 h60
  text ".VersionControl_RevNumber" at 4982,-655.67 h60
  text "IGNORE ->" at -228.5,-858.49 h60
  text "PLOT NAME =" at -228.5,-1064.34 h60
  text ".plot_File_Name" at 577,-1064.34 h60
  text "GENERATED    :" at 2250,-1064.34 h60
  text ".Print_Date" at 3119.5,-1064.34 h60
  text ".Print_Time" at 3848.5,-1064.34 h60
  text "TEXAS INSTRUMENTS" at 5113,-1064.34 h60
M6 Assembly Bottom:
  circle w6: c7677,1594 r4
  circle w6: c734,1597 r2
  circle w6: c1843,1598 r3
  circle w6: c2961,1593 r3
  circle w6: c3902,1597 r3
  lines w6: 512.32,1738.5 512.32,1801.5 ; 567.68,1738.5 567.68,1801.5 ; 1013.5,1982.32 1076.5,1982.32 ; 1013.5,2037.68 1076.5,2037.68 ; 1622.32,1738.5 1622.32,1801.5 ; 1677.68,1738.5 1677.68,1801.5 ; 2128.5,1982.32 2191.5,1982.32 ; 2128.5,2037.68 2191.5,2037.68 ; 2742.32,1738.5 2742.32,1801.5 ; 2797.68,1738.5 2797.68,1801.5 ; 3248.5,1982.32 3311.5,1982.32 ; 3248.5,2037.68 3311.5,2037.68 ; 3667.31,1713.5 3667.31,1776.5 ; 3722.69,1713.5 3722.69,1776.5 ; 7442.31,1718.5 7442.31,1781.5 ; 7497.69,1718.5 7497.69,1781.5
  lines w10: -292.5,-727.33 6309.5,-727.33 ; -290.5,-930.67 6309.5,-930.67 ; 1115.5,-1140.5 1115.5,-937.67 ; 1737.5,-727.33 1737.5,-524 ; 2577.5,-727.33 2577.5,-524 ; 3844.5,-1134 3844.5,-524 ; 4733.5,-1134 6309,-1134 6309,-524 -292.5,-524 -292.5,-1134 2304.5,-1134 6309.5,-1134 6309.5,-524
  text "FB2" at 2198,1995 h30
  text "FB5" at 3318,1995 h30
  text "FB1" at 1083,1992 h36
  text "FB3" at 525,1732 h30 r270
  text "FB4" at 1635,1732 h30 r270
  text "FB7" at 2755,1732 h30 r270
  text "FB9" at 3680,1707 h30 r270
  text "FB8" at 7361,1698 h50 r270
  text "COMPONENTS MARKED 'DNP' SHOULD NOT BE POPULATED." at 6102,-318 h60
  text ".VariantName" at 5058,-434 h60
  text "ASSEMBLY VARIANT:" at 6097,-434 h60
  text ".VersionControl_RevNumber" at 1035.5,-656.17 h60
  text "SVN REV:" at 1541.5,-656.17 h60
  text "E2" at 2088,-656.17 h60
  text "REV:" at 2379.5,-656.17 h60
  text ".PRJ_Number" at 3224,-656.17 h60
  text "BOARD #:" at 3769.5,-656.17 h60
  text "PCB VIEWED FROM BOTTOM SIDE" at 6246,-656.17 h60
  text "IGNORE ->" at 2547.85,-858.49 h60
  text "TEXAS INSTRUMENTS" at 904.5,-1064.84 h60
  text ".Print_Time" at 2169,-1064.84 h60
  text ".Print_Date" at 2898,-1064.84 h60
  text "GENERATED    :" at 3767.5,-1064.84 h60
  text ".plot_File_Name" at 5440.5,-1064.84 h60
  text "PLOT NAME =" at 6246,-1064.84 h60
M7 LPKF Text Top:
  lines w10: 3650,420 3650,2570 ; 4070,335 4070,2440 ; 4170,-125 4170,2435 ; 4840,-120 4840,2445 ; 4940,-130 4940,2435 ; 4940,-50 4940,2515 ; 5040,-60 5040,2505 ; 5710,-170 5710,2440 ; 5710,-145 5710,2435 ; 5710,-35 5710,2530 ; 5810,-85 5810,2480 ; 5810,-45 5810,2520 ; 5910,-95 5910,2470 ; 6380,-165 6380,2440 ; 7028,-165 7028,2430
M9 Title Sheet:
  drawing of 57 lines, arcs and shapes, not listed
  text "1" at 739.84,8036.5 h70
  text "2" at 3235.5,8036.5 h70
  text "3" at 5724.84,8036.5 h70
  text "4" at 8231.51,8036.5 h70
  text "5" at 10730.5,8036.5 h70
  text "6" at 13235.5,8036.5 h70
  text "A" at -416.5,6893.5 h70
  text "A" at 14383.5,6893.5 h70
  text "B" at -416.5,4513.5 h70
  text "B" at 14383.5,4513.5 h70
  text "C" at -416.5,2138.5 h70
  text "C" at 14383.5,2138.5 h70
  text "PROJECT TITLE:" at 11343.5,277.5 h45
  text ".prj_Title" at 11393.5,144.17 h70
  text "DESIGNED FOR:" at 11343.5,-23.5 h45
  text ".PRJ_Customer" at 11393.5,-163.5 h70
  text "D" at -416.5,-231.5 h70
  text "D" at 14383.5,-231.5 h70
  text "FILE NAME:" at 11343.5,-323.5 h45
  text ".PCB_File_Name_No_Path" at 11393.5,-443.5 h70
  text "Texas Instruments (TI) and/or its licensors do not warrant the accuracy or completeness of this specification" at 6374,-605.34 h45
  text "ENGINEER:" at 11343.5,-613.5 h45
  text "LAYOUT BY:" at 12848.5,-613.5 h45
  text "or any information contained therein. TI and/or its licensors do not warrant that this design will meet" at 6329.01,-718 h45
  text ".PRJ_Engineer" at 11393.5,-768.49 h60
  text ".PCB_Layout" at 12899,-768.49 h60
  text "the specifications, will be suitable for your application or fit for any particular purpose, or will operate in" at 6329.01,-830.67 h45
  text "ALTIUM DESIGNER VERSION:" at 12848.5,-923.5 h45
  text "an implementation. TI and/or its licensors do not warrant that the design is production worthy. You should" at 6329.01,-943.33 h45
  text "completely validate and test your design implementation to confirm the system functionality for your application." at 6374,-1056 h45
  text ".print_Scale" at 11393.5,-1056.83 h70
  text ".Application_BuildNumber" at 12899,-1056.83 h70
  text "1" at 739.84,-1263.5 h70
  text "2" at 3235.5,-1263.5 h70
  text "3" at 5724.84,-1263.5 h70
  text "4" at 8231.51,-1263.5 h70
  text "5" at 10730.5,-1263.5 h70
  text "6" at 13235.5,-1263.5 h70
M10 Fab Notes:
  drawing of 215 lines, arcs and shapes, not listed
  text "DESIGN INFORMATION" at 12381.02,6810 h60
  text "(REFER ALSO ARRAY/PANEL PROFILING INFORMATION)" at 12019.46,6648.29 h60
  text "BOARD SIZE" at 11333.46,6644 h60
  text "X" at 12301.46,6516.18 h60
  text "7874MIL" at 11830,6510 h60
  text "2559MIL" at 12520,6510 h60
  text "Number of Layers :" at 11691.46,6419 h60
  text "4" at 12786.27,6409 h60
  text "MIN. TRACK WIDTH:" at 11691.46,6280 h60
  text "8" at 12787.7,6280 h60
  text "MIL" at 12942.46,6280 h60
  text "MIN. CLEARANCE:" at 11691.46,6148 h60
  text "8" at 12787.7,6148 h60
  text "MIL" at 12942.46,6148 h60
  text "MIN. VIA PAD SIZE:" at 11691.46,6016 h60
  text "32" at 12757.71,6016 h60
  text "MIL" at 12942.46,6016 h60
  text "0.05mm (2MIL)" at 12386.46,5874.29 h60
  text "MINIMUM ANNULAR RING" at 11362.23,5870 h60
  text "EXTERNAL" at 13094.46,5870 h60
  text "PER" at 11562.23,5752 h60
  text "IPC-D-275 CLASS 2 LEVEL C" at 11782.23,5752 h60
  text "MIL, HOLES" at 13270.46,5639.71 h60
  text "+/-" at 12878,5639 h60
  text "+/-" at 13732,5639 h60
  text "REGISTRATION TOLERANCES:" at 11362.23,5634 h60
  text "METAL" at 12562,5634 h60
  text "5" at 13138.2,5634 h60
  text "3" at 13971.2,5634 h60
  text "MIL" at 14110,5630 h60
  text "VIA'S ARE TENTED" at 11562.23,5517 h60
  text "IT IS NOT IMPEDANCE CONTROLLED BOARD" at 11567.23,5417 h60
  text "MATERIAL:" at 11345,5315 h60
  text "FR-4 High Tg" at 12318.9,5184.21 h60
  text "FR-408" at 11753.46,5175.64 h60
  text "X" at 12165.46,5175.64 h60
  text "OTHER" at 13241.46,5175.64 h60
  text "62 MIL (1.6mm) +/-10%" at 12073.56,5012.92 h60
  text "THICKNESS:" at 11407.23,5008.64 h60
  text "X" at 11945.4,5008.64 h60
  text "OTHER" at 13358.46,5008.64 h60
  text "TOLERANCE:" at 11407.23,4850.64 h60
  text "X" at 12246.53,4850.64 h60
  text "ANSI IPC-6012 TYPE 3 CLASS 2" at 12433.48,4850.64 h60
  text "OTHER +/-" at 12433.46,4694.64 h60
  text "BOW & TWIST:" at 11407.23,4537.64 h60
  text "X" at 12246.53,4537.64 h60
  text "ANSI IPC-6012 TYPE 3 CLASS 2" at 12433.48,4537.64 h60
  text "OTHER +/-" at 12433.46,4379.13 h60
  text "COPPER THICKNESS (FINISHED):" at 11332.46,4243.64 h60
  text "1.4MIL (1oz)" at 12212.46,4090.92 h60
  text "2MIL (1.4oz)" at 12979.46,4090.92 h60
  text "2.8MIL (2oz)" at 13706.46,4090.92 h60
  text "OUTER:" at 11689.46,4086.64 h60
  text "X" at 13580,4080 h60
  text "X" at 12855,3940 h60
  text "1.4MIL (1oz)" at 12212.46,3933.92 h60
  text "2.8MIL (2oz)" at 12979.46,3933.92 h60
  text "N/A" at 13706,3934.29 h60
  text "INNER SIGNAL:" at 11400.38,3929.64 h60
  text "DRILLING:" at 11332.46,3790.64 h60
  text "REFERENCE:" at 11407.23,3673.64 h60
  text "X" at 12055.46,3673.64 h60
  text "AS SHOWN" at 12242.46,3673.64 h60
  text "X" at 12956.46,3673.64 h60
  text "NC_DRILL FILES" at 13093.46,3673.64 h60
  text "PTH MIN COPPER THICKNESS:" at 11407.23,3515.64 h60
  text "X" at 12757.46,3515.64 h60
  text "1MIL" at 12894.46,3515.64 h60
  text "OTHER" at 13391.46,3515.64 h60
  text "BOARD FINISH:" at 11332.46,3356.64 h60
  text "SILKSCREEN:" at 11487.68,3238.64 h60
  text "X" at 12436.46,3238.64 h60
  text "TOP" at 12562.46,3238.64 h60
  text "X" at 12946.46,3238.64 h60
  text "BOTTOM" at 13073.46,3238.64 h60
  text "SILKSCREEN COLOR:" at 11487.68,3071.64 h60
  text "X" at 12435.42,3071.64 h60
  text "WHITE" at 12562.46,3071.64 h60
  text "OTHER" at 13073.46,3071.64 h60
  text "SOLDER RESIST COLOR:" at 11487.68,2901.64 h60
  text "X" at 12055.42,2742.44 h60
  text "GREEN" at 12182.46,2742.44 h60
  text "BLUE" at 12773.46,2742.44 h60
  text "OTHER" at 13311.46,2742.44 h60
  text "IMMERSION GOLD (ENIG)" at 12393.46,2553.92 h60
  text "ENEPIG" at 13731,2550.64 h60
  text "SURFACE FINISH:" at 11332.46,2549.64 h60
  text "X" at 12206.51,2549.64 h60
  text "IMM. TIN/SILVER OR EQUIV" at 11662,2392.64 h60
  text "OTHER" at 13093.46,2392.64 h60
  text "ARRAY/PANEL:" at 11332.46,2213.64 h60
  text "CUT AND TRIM PER MECH LAYER 1" at 12393.46,2209.35 h60
  text "N.C. ROUTE" at 12393.46,2057.64 h60
  text "X" at 13072.46,2057.64 h60
  text "V. SCORE" at 13259.46,2057.64 h60
  text "CERTIFICATION:" at 11332.46,1920.64 h60
  text "MATERIALS AND WORKMANSHIP FOR ALL PCBS" at 12057.46,1920.64 h60
  text "TO MEET OR EXCEED THE REQUIREMENTS OF:" at 12057.46,1822.64 h60
  text "X" at 11683.96,1686.13 h60
  text "ANSI IPC-A-600F CLASS ->" at 11822.96,1686.13 h60
  text "X" at 13462.02,1686.13 h60
  text "2" at 13580.96,1686.14 h60
  text "1" at 13265.96,1684.64 h60
  text "3" at 13934.96,1684.64 h60
  text "X" at 11686.02,1526.64 h60
  text "UL 94V-0" at 11822.96,1526.64 h60
  text "X" at 12498.02,1526.64 h60
  text "RoHS" at 12634.96,1526.64 h60
  text "OTHER" at 13279.36,1526.64 h60
  text "PER ORDER" at 13676.42,1526.64 h60
  text "ADDITIONAL REQUIREMENTS:" at 11332.46,1385.64 h60
  text "MICROSECTION:" at 11407.23,1270.64 h60
  text "YES" at 12312.96,1270.64 h60
  text "REQUIRED" at 13174.46,1114.49 h60
  text "BARE BOARD ELEC. TEST:" at 11407.23,1111.64 h60
  text "NONE" at 12712.96,1111.64 h60
  text "X" at 13047.46,1111.64 h60
  text "PER ORDER" at 13766.46,1111.64 h60
  text "MANUFACTURER'S UL:" at 11407.23,954.64 h60
  text "RAIL" at 12572.96,950.35 h60
  text "METAL" at 13064.77,950.35 h60
  text "X" at 13440,950 h60
  text "SILK" at 13576.46,950.35 h60
M11 Gerber Information:
  lines w10: -292,-930.17 6308,-930.17 ; -292,-726.83 6310,-726.83 ; -292,-523.5 -292,-1133.5 3713,-1133.5 6310,-1133.5 6310,-523.5 -291.5,-523.5 -291.5,-1133.5 1284,-1133.5 ; 2173,-1133.5 2173,-523.5 ; 3440,-726.83 3440,-523.5 ; 4280,-726.83 4280,-523.5 ; 4902,-1140 4902,-937.17
  text "ALL ARTWORK VIEWED FROM TOP SIDE" at -228.5,-655.67 h60
  text "BOARD #:" at 2248,-655.67 h60
  text "REV:" at 3638,-655.67 h60
  text "E2" at 3929.5,-655.67 h60
  text "SVN REV:" at 4476,-655.67 h60
  text ".VersionControl_RevNumber" at 4982,-655.67 h60
  text ".PRJ_Number" at 2700,-660 h50
  text "LAYER NAME =" at -228.5,-858.49 h60
  text "PLOT NAME =" at -228.5,-1064.34 h60
  text ".plot_File_Name" at 577,-1064.34 h60
  text "GENERATED    :" at 2250,-1064.34 h60
  text ".Print_Date" at 3119.5,-1064.34 h60
  text ".Print_Time" at 3848.5,-1064.34 h60
  text "TEXAS INSTRUMENTS" at 5113,-1064.34 h60
M12 Stackup:
  lines w6: 11365,7700.5 14240,7700.5 ; 11365,7813.1 14240,7813.1 ; 11305,6976 ccw(c11341,6976) 11341,6940 14264,6940 ccw(c14264,6976) 14300,6976 14300,7914 ccw(c14264,7914) 14264,7950 11341,7950 ccw(c11341,7914) 11305,7914 11305,6976
  text "Layer Stack Up Detail for: ISE_MCS_SDM_E2.PcbDoc" at 11365,7842.95 h52
  text "Layer" at 11365,7771.1 h26
  text "Gerber" at 12371.14,7771.1 h26
  text "Copper" at 13031.52,7771.1 h26
  text "Dielectric" at 13734.35,7771.1 h26
  text "Name" at 11365,7719.1 h26
  text "Document" at 12371.14,7719.1 h26
  text "Thickness" at 13031.52,7719.1 h26
  text "Material" at 13734.35,7719.1 h26
  text "Top Solder Mask" at 11365,7644.9 h36
  text "(.GTS)" at 12371.14,7644.9 h36
  text "Solder Resist" at 13734.35,7644.9 h36
  text "Top Layer" at 11365,7539.69 h36
  text "(.GTL)" at 12371.14,7539.69 h36
  text "2.8mil" at 13031.52,7539.69 h36
  text "FR-4 High Tg" at 13734.35,7487.08 h36
  text "MidLayer1" at 11365,7434.48 h36
  text "(.G1)" at 12371.14,7434.48 h36
  text "2.8mil" at 13031.52,7434.48 h36
  text "FR-4 High Tg" at 13734.35,7381.88 h36
  text "MidLayer2" at 11365,7329.27 h36
  text "(.G2)" at 12371.14,7329.27 h36
  text "2.8mil" at 13031.52,7329.27 h36
  text "FR-4 High Tg" at 13734.35,7276.67 h36
  text "Bottom Layer" at 11365,7224.06 h36
  text "(.GBL)" at 12371.14,7224.06 h36
  text "2.8mil" at 13031.52,7224.06 h36
  text "Bottom Solder Mask" at 11365,7118.85 h36
  text "(.GBS)" at 12371.14,7118.85 h36
  text "Solder Resist" at 13734.35,7118.85 h36
M13 Component Bodies Top:
  text ".Layer_Name" at 577,-858.49 h60
M14 Component Bodies Bottom:
  text ".Layer_Name" at 577,-858.49 h60
M15 Courtyards Top:
  text ".Layer_Name" at 577,-858.49 h60
M16 Courtyards Bottom:
  text ".Layer_Name" at 577,-858.49 h60
Drill Drawing:
  text ".legend" at 30,3985 h60
  text "Drill Table" at 40,3840 h60
  text ".Layer_Name" at 577,-858.49 h60

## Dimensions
7736.22,2421.26 to 7874.02,2559.06 on M1 Board Outline
7736.22,2421.26 to 7874.02,2559.06 on M1 Board Outline
0,2559.06 to 7874.02,2559.06 on M1 Board Outline
0,0 to 5,2559.06 on M1 Board Outline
